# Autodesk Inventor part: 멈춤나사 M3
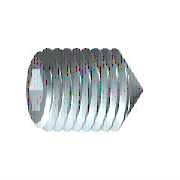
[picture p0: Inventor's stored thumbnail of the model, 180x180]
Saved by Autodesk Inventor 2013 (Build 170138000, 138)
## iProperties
Created: 2012-02
Part Number: 멈춤나사 M3
Material: 강철, 연강
Description: 6각 소켓 머리 없는 멈춤 나사
Document SubType Name: Modeling
Standard: KS B 1028
Designer: mduedu
Standards Organization: KS
Language: ko-KR
Size Designation: 원추점 M3x8
Categories: <MemberInstance><Categories><Category DisplayName="조임쇠" InternalName="e4da775c-781d-43d5-af7c-5136215cf5a6" Mnemonic="FSTN"><Category DisplayName="볼트" InternalN
Density: 7.86 g/cm^3
Mass: 0.360339 g
Surface Area: 0.888172 cm^2
Volume: 0.0458447 cm^3
IsCustomPart: 1
Author: mduedu
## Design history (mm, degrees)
sketch "스케치1"
  geometry: L1 (0, 0)-(5.5, 0); L2 (8, 0.866)-(8, 1.5); L3 (8, 1.5)-(0, 1.5); L4 (8, 0.866)-(6, 0.866); L5 (6, 0.866)-(5.5, 0); L6 (0, -0.3)-(0, 1.8) reference; L7 (0, 1.5)-(0, 0)
  constraints: 13 end point, 3 parallel, 1 collinear, 1 perpendicular, 1 point on line
  dimensions: "d0" = 2 distance of L2.start L4.end (= INTI); "d1" = 60 deg angle of L5 L1; "d2" = 3 diameter of L3 L1 (= NND); "d3" = 1.73205 diameter of L4 L1 (= 1.1547 x SW); "d5" = 8 distance from line of L2 L3.end (= NLG)
revolve "본체" sketch "스케치1" stored, may be unused: angle "d6" = 90 deg
sketch "스케치2"
  geometry: L1 (-0.433, 0.75)-(0.433, 0.75); L2 (0.433, 0.75)-(0.866, 0); L3 (0.866, 0)-(0.433, -0.75); L4 (0.433, -0.75)-(-0.433, -0.75); L5 (-0.433, -0.75)-(-0.866, 0); L6 (-0.866, 0)-(-0.433, 0.75); 3 further points
  constraints: 12 end point, 1 coincident, 1 horizontal, 13 other
extrude "슬롯" join sketch "스케치2" taper "d7" = 0 deg; stored distance "d21" = 10
workaxis "Work Axis1"
workplane "Work Plane1"
sketch "스케치5"
  geometry: L1 (-4, -0.15)-(-2.65, -1.5) reference; L2 (-4, 0.15)-(-2.65, 1.5) reference; L3 (-2.65, 1.5)-(-4.15, 0); L4 (-2.65, -1.5)-(-4.15, 0); 1 further point
  constraints: 4 end point, 1 horizontal alignment, 1 perpendicular
node "작업점1"
body "Solid1"
feature "스레드" dims "d12" = 8 (= NLG), "d13" = 0
chamfer "모따기1" distance "d8" = 1.35 (computed from NND, SPD, FAWI); stored, may be unused: angle "d9" = 45 deg (= FAWI), second distance "d34" = 1.35 (computed from NND, SPD, FAWI)
chamfer "모따기2" distance "d10" = 0.30673 (= -0.5 x GD1 + 0.5 x NND); stored, may be unused: angle "d11" = 45 deg (= FAWI), second distance "d35" = 0.30673 (= -0.5 x GD1 + 0.5 x NND)
other parameters: "NND" = 3 [user parameter; used in 5 equation terms], "NLG" = 8 [user parameter; used in 2 equation terms], "INTI" = 2 [user parameter; used in 1 equation term], "FAWI" = 45 deg [user parameter; used in 4 equation terms], "SW" = 1.5 [user parameter; used in 2 equation terms], "GD1" = 2.38655 (= THREADDIA - 1.2269 x PTC) [user parameter; used in 2 equation terms], "d4" = 0, "FAWI1" = 45 deg [user parameter], "SPD" = 0.3 [user parameter; used in 2 equation terms], "d36" = 0, "d37" = 0, "GUL" = 0.30673 (= 0.61345 x PTC) [user parameter], "TOA" = 30 deg [user parameter], "THREADDIA" = 3 [user parameter; used in 1 equation term], "PTC" = 0.5 [user parameter; used in 4 equation terms], "GAL" = 0.30673 (= 0.61345 x PTC) [user parameter], "E0" = 1.7325 (= 1.155 x SW) [user parameter]
